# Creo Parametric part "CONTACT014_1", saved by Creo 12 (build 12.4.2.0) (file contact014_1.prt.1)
Units: Custom; MM, KILOGRAM, SECS

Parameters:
  PTC_WM_ITERATION = "0"
  PTC_WM_VERSION = "-.0"
  PTC_WM_LIFECYCLE_STATE = "In Work"
  PTC_WM_LIFECYCLE = "MO_CADDocument"
  PTC_WM_CREATED_BY = "Maximilian Roepper (Z0017RMS: MO)"
  PTC_WM_CREATED_ON = "18-Sep-26 11:36:42 AM"
  PTC_WM_MODIFIED_BY = "Maximilian Roepper (Z0017RMS: MO)"
  PTC_WM_MODIFIED_ON = "18-Sep-26 11:36:46 AM"
  PDMLINKNUMBER = "PDM000071455104"
  PTC_WM_NAME = "contact014_1.prt"
  PTC_WM_NUMBER = "PDM000071455104"

Other parameters: WEIGHT, WEIGHT_FACTOR, WEIGHT_ADD, _MASS_TEMP, _DIFF_TEMP, MC_ERRORS, SUPPLIER

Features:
  1. coordinate system
  2. datum plane "PRT_YZ"
  3. datum plane "PRT_XY"
  4. datum plane "PRT_XZ"
  5. coordinate system
  6. datum axis
  7. datum axis
  8. datum axis
  9. coordinate system
  10. imported feature

Other named items: PRT, SIEMENS_MO, DRW_VIEW_ORG, PRT_X, PRT_Y, PRT_Z, CS0, ROUGH_GROB

Layers: 00_STD_CSYS-KSYS, 01_STD_PLANES-EBENEN, 02_STD_AXES-ACHSEN, 03_STD_CSYS-KSYS, 24_IMPORT_FEAT-IMPORT_KE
